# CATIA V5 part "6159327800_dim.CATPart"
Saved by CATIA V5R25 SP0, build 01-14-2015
Part number: 6159327800_dim
Source: made
Property "PROI_CREATED_ON": "12/17/2008 9:21:37 AM"
Property "BLANK_DRAWING": "--"
Property "DRAWN_BY": "ALG"
Property "FINISH": "--"
Property "HEAT_TREATMENT": "ASSIGN"
Property "MATERIAL": "ASSIGN"
Property "PROJECT": "--"
Property "PROTOTYPE_NO": "--"
Property "RELATED_DRAWING": "--"
Property "COMPLETE_MATERIAL": "ASSIGN-ASSIGN"
Property "DESCRIPTION": "AXD"
Property "DRAWING_EXIST": "--"
Property "MANUFACTURER": "--"
Property "MANUFACTURER_2": "--"
Property "MANUFACTURER_REF": "--"
Property "TYPE_PART": "A"
Property "TODAY_DATE": "2025/05/15"
Property "PDMREV": "01.0"
Property "PDMRL": "Production"
Property "PROI_REVISION": "01"
Property "PROI_VERSION": "0"
Property "PROI_RELEASE": "Production"
Property "PTC_MODIFIED": false
Property "MFG_WP_MATERIAL": "ASSIGN"
Property "COMPANY_CODE": "---"
Property "DESCRIPTION_JP": "--"
Property "PQP_DOCUMENT": "--"
Property "SUPPLIER": "--"
Property "REFERENCE": "6159327800"
Property "PTC_WM_REVISION": "01"
Property "PTC_WM_ITERATION": "0"
Property "PTC_WM_VERSION": "01.0"
Property "PTC_WM_LIFECYCLE_STATE": "Production"
Property "PTC_WM_LIFECYCLE": "Design_Process"
Property "PTC_WM_LOCATION": "/Products/CONTROLLERS/A1770 - CX4 - SMART DRIVE - LEAN/9-01-Dimensional Drawings"
Property "PTC_WM_CREATED_BY": "Alain Le Goc (grealg) (grealg: CPD)"
Property "PTC_WM_CREATED_ON": "15-May-25 11:41:09 AM"
Property "PTC_WM_MODIFIED_BY": "Alain Le Goc (grealg) (grealg: CPD)"
Property "PTC_WM_MODIFIED_ON": "15-May-25 02:30:15 PM"
Property "PTC_WM_TEAM": "Default"
Property "PTC_ORGANIZATION_ID": "CPD"
Property "PTC_WM_NAME": "6159327800_dim.prt"
Property "PTC_WM_NUMBER": "6159327800_DIM.PRT"
Property "PTC_COMMON_NAME": "6159327800_dim.prt"
Property "PTC_MASTER_MATERIAL": "ASSIGN"
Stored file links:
  d:\ptc\Echange\temp\6159327800_dim.CATPart

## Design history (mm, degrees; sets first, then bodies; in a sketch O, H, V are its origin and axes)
AxisSystem1 "CS0": origin (0, 0, 0), X (1, 0, 0), Y (0, 1, 0), Z (0, 0, 1)
Set1
  DatumSurface1 "Sheet.1"
  DatumSurface2 "Sheet.2"
  DatumSurface3 "Sheet.3"
  DatumSurface4 "Sheet.4"
  DatumSurface5 "Sheet.5"
  DatumSurface6 "Sheet.6"
  DatumSurface7 "Sheet.7"
  DatumSurface8 "Sheet.8"
  DatumSurface9 "Sheet.9"
  DatumSurface10 "Sheet.10"
  DatumSurface11 "Sheet.11"
  DatumSurface12 "Sheet.12"
  DatumSurface13 "Sheet.13"
  DatumSurface14 "Sheet.14"
  DatumSurface15 "Sheet.15"
  DatumSurface16 "Sheet.16"
  DatumSurface17 "Sheet.17"
  DatumSurface18 "Sheet.18"
  DatumSurface19 "Sheet.19"
  DatumSurface20 "Sheet.20"
  DatumSurface21 "Sheet.21"
  DatumSurface22 "Sheet.22"
  DatumSurface23 "Sheet.23"
  DatumSurface24 "Sheet.24"
  DatumSurface25 "Sheet.25"
  DatumSurface26 "Sheet.26"
  DatumSurface27 "Sheet.27"
  DatumSurface28 "Sheet.28"
  DatumSurface29 "Sheet.29"
  DatumSurface30 "Sheet.30"
  DatumSurface31 "Sheet.31"
  DatumSurface32 "Sheet.32"
  DatumSurface33 "Sheet.33"
  DatumSurface34 "Sheet.34"
  DatumSurface35 "Sheet.35"
  DatumSurface36 "Sheet.36"
  DatumSurface37 "Sheet.37"
  DatumSurface38 "Sheet.38"
  DatumSurface39 "Sheet.39"
  DatumSurface40 "Sheet.40"
  DatumSurface41 "Sheet.41"
  DatumSurface42 "Sheet.42"
  DatumSurface43 "Sheet.43"
  DatumSurface44 "Sheet.44"
  DatumSurface45 "Sheet.45"
  DatumSurface46 "Sheet.46"
  DatumSurface47 "Sheet.47"
  DatumSurface48 "Sheet.48"
  DatumSurface49 "Sheet.49"
  DatumSurface50 "Sheet.50"
  DatumSurface51 "Sheet.51"
  DatumSurface52 "Sheet.52"
  DatumSurface53 "Sheet.53"
  DatumSurface54 "Sheet.54"
  DatumSurface55 "Sheet.55"
  DatumSurface56 "Sheet.56"
  DatumSurface57 "Sheet.57"
  DatumSurface58 "Sheet.58"
  DatumSurface59 "Sheet.59"
  DatumSurface60 "Sheet.60"
  DatumSurface61 "Sheet.61"
  DatumSurface62 "Sheet.62"
  DatumSurface63 "Sheet.63"
  DatumSurface64 "Sheet.64"
  DatumSurface65 "Sheet.65"
  DatumSurface66 "Sheet.66"
  DatumSurface67 "Sheet.67"
  DatumSurface68 "Sheet.68"
  DatumSurface69 "Sheet.69"
  DatumSurface70 "Sheet.70"
  DatumSurface71 "Sheet.71"
  DatumSurface72 "Sheet.72"
  DatumSurface73 "Sheet.73"
  DatumSurface74 "Sheet.74"
  DatumSurface75 "Sheet.75"
  DatumSurface76 "Sheet.76"
  DatumSurface77 "Sheet.77"
  DatumSurface78 "Sheet.78"
  DatumSurface79 "Sheet.79"
  DatumSurface80 "Sheet.80"
  DatumSurface81 "Sheet.81"
  DatumSurface82 "Sheet.82"
  DatumSurface83 "Sheet.83"
  DatumSurface84 "Sheet.84"
  DatumSurface85 "Sheet.85"
  DatumSurface86 "Sheet.86"
  DatumSurface87 "Sheet.87"
  DatumSurface88 "Sheet.88"
  DatumSurface89 "Sheet.89"
  DatumSurface90 "Sheet.90"
  DatumSurface91 "Sheet.91"
  DatumSurface92 "Sheet.92"
  DatumSurface93 "Sheet.93"
  DatumSurface94 "Sheet.94"
  Plane1 "RIGHT": stored without definition
  Plane2 "TOP": stored without definition
  Plane3 "FRONT": stored without definition
Body1 "PartBody" (main body)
